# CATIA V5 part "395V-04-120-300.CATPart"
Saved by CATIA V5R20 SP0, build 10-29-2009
Part number: 395V-04-120-300
Source: Unknown
Property "A": "60.000"
Property "ARTICLENO": "395V-04-120-300"
Property "BOMINFO": "395V-04-120-300"
Property "CODE": "395V-04-120-300"
Property "D": "100.000"
Property "D1": "33.000"
Property "D2": "48.000"
Property "D3": "130.000"
Property "FORM": "B"
Property "L": "300.000"
Property "L1": "30.000"
Property "L2": "125.000"
Property "L3": "80.000"
Property "L4": "15.000"
Property "LINA": "395V-04-120-300"
Property "MAXLOAD": "20000 Kg"
Property "MDW": "40000 Kg"
Property "NB": "395V-04-120-300"
Property "NBSYN": "$CODE."
Property "NN": "395V"
Property "NT": "VDI 3366 Lifting Brackets"
Property "SUPPLIER": "CF"
Property "T": "32.000"
Property "W": "120.000"
Bounding box of the stored display mesh (mm): x -60 to 60, y 0 to 300, z -60 to 60
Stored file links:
  C:\Users\Utente\Desktop\3D files 395V\395V-04-120-300.CATPart
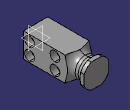
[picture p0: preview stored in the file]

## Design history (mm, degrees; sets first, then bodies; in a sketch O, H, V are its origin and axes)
Body1 "Geometry.1" (main body)
  Solid1 "395V-04-120-300.catpart": solid without history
